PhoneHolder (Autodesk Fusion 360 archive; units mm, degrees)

design "PhoneHolderScrew" references "PhoneClamp"
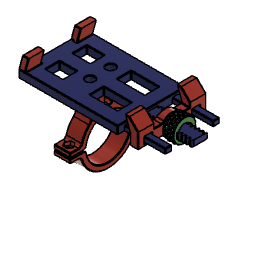
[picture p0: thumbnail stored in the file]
parameter "ScrewTolerance" = 0.1
parameter "NutTolerance" = 0
sketch "Sketch1" plane through (0, 0, 0) normal (0, 0, 1) x axis (1, 0, 0)
  line L1 (-12.5, 50) -> (-85, 50)
  line L2 (-12.5, 0) -> (-12.5, 50)
  line L3 (-85, 0) -> (-12.5, 0)
  line L4 (-85, 50) -> (-85, 0)
  line L5 (-52.5, 20) -> (-52.5, 35)
  line L6 (-80, 48) -> (-83, 48)
  line L7 (-80, 38) -> (-80, 48)
  line L8 (-83, 38) -> (-80, 38)
  line L9 (-83, 48) -> (-83, 38)
  line L10 (-80, 2) -> (-83, 2)
  line L11 (-80, 12) -> (-80, 2)
  line L12 (-83, 12) -> (-80, 12)
  line L13 (-83, 2) -> (-83, 12)
  line L14 (17.5, 45) -> (-12.5, 45)
  line L15 (17.5, 40) -> (17.5, 45)
  line L16 (-12.5, 40) -> (17.5, 40)
  line L17 (-12.5, 45) -> (-12.5, 40)
  line L18 (17.5, 5) -> (-12.5, 5)
  line L19 (17.5, 10) -> (17.5, 5)
  line L20 (-12.5, 10) -> (17.5, 10)
  line L21 (-12.5, 5) -> (-12.5, 10)
  line L22 (-80, 25) -> (-12.5, 25)
  line L23 (-22.5, 40) -> (-42.5, 40)
  line L24 (-22.5, 30) -> (-22.5, 40)
  line L25 (-42.5, 30) -> (-22.5, 30)
  line L26 (-42.5, 40) -> (-42.5, 30)
  line L27 (-22.5, 20) -> (-42.5, 20)
  line L28 (-22.5, 10) -> (-22.5, 20)
  line L29 (-42.5, 10) -> (-22.5, 10)
  line L30 (-42.5, 20) -> (-42.5, 10)
  line L31 (-75, 30) -> (-62.5, 30)
  line L32 (-75, 40) -> (-75, 30)
  line L33 (-62.5, 40) -> (-75, 40)
  line L34 (-62.5, 30) -> (-62.5, 40)
  line L35 (-75, 10) -> (-62.5, 10)
  line L36 (-75, 20) -> (-75, 10)
  line L37 (-62.5, 20) -> (-75, 20)
  line L38 (-62.5, 10) -> (-62.5, 20)
  circle C1 centre (-52.5, 35) radius 1.75
  circle C2 centre (-52.5, 20) radius 1.75
  circle C3 centre (-52.5, 35) radius 3
  circle C4 centre (-52.5, 20) radius 3
  point P6 (-52.5, 35)
  point P8 (-52.5, 35)
  point P7 (-52.5, 20)
  point P9 (-52.5, 20)
  point P20 (-12.5, 45)
  point P24 (-12.5, 5)
  point P28 (-12.5, 25)
  point P2 (-85, 50)
  point P3 (-12.5, 50)
  point P5 (-85, 0)
  point P10 (-52.5, 35)
  point P21 (17.5, 45)
  horizontal L1
  vertical L2
  horizontal L3
  vertical L4
  vertical L5
  coincident P6 P8
  coincident P7 P9
  concentric C1 C3
  concentric C2 C4
  horizontal L6
  vertical L7
  horizontal L8
  vertical L9
  horizontal L10
  vertical L11
  horizontal L12
  vertical L13
  horizontal L14
  vertical L15
  horizontal L16
  vertical L17
  coincident L2 P20
  horizontal L18
  vertical L19
  horizontal L20
  vertical L21
  coincident L2 P24
  midpoint L2 P28
  perpendicular L5 L22
  horizontal L23
  vertical L24
  horizontal L25
  vertical L26
  horizontal L27
  vertical L28
  horizontal L29
  vertical L30
  horizontal L31
  vertical L32
  horizontal L33
  vertical L34
  horizontal L35
  vertical L36
  horizontal L37
  vertical L38
  dimension "d1" distance P2 P3 = 72.5
  dimension "d2" distance P2 P5 = 50
  dimension "d3" distance P6 P7 = 15
  dimension "d4" diameter C1 = 3.5
  dimension "d5" diameter C2 = 3.5
  dimension "d6" diameter C3 = 6
  dimension "d7" diameter C4 = 6
  dimension "d8" distance L4 L5 = 32.5
  dimension "d9" distance L1 P10 = 15
  dimension "d10" distance L6 L8 = 10
  dimension "d11" distance L7 L9 = 3
  dimension "d12" distance L1 L6 = 2
  dimension "d13" distance L4 L9 = 2
  dimension "d14" distance L10 L12 = 10
  dimension "d15" distance L11 L13 = 3
  dimension "d16" distance L4 L13 = 2
  dimension "d17" distance L3 L10 = 2
  dimension "d18" distance P20 P21 = 30 (= "d21")
  dimension "d19" distance L14 L16 = 5
  dimension "d20" distance L1 L14 = 5
  dimension "d21" distance L2 L19 = 30
  dimension "d22" distance L18 L20 = 5
  dimension "d23" distance L3 L18 = 5
  dimension "d186" distance L32 L34 = 12.5
  dimension "d187" distance L36 L38 = 12.5 (= "d186")
  dimension "d188" distance L4 L32 = 10
  dimension "d189" distance L4 L36 = 10 (= "d188")
  dimension "d190" distance L2 L24 = 10
  dimension "d191" distance L2 L28 = 10 (= "d190")
  dimension "d192" distance L24 L26 = 20
  dimension "d193" distance L28 L30 = 20 (= "d192")
  dimension "d194" distance L23 L25 = 10
  dimension "d195" distance L27 L29 = 10 (= "d194")
extrude "Extrude1" new body sketch "Sketch1" profile of L1 L2 L3 L4 C1 C2 C3 C4 L6 L7 L8 L9 L10 L11 L12 L13 L14 L15 L16 L17 L18 L19 L20 L21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 along normal blind 1.2
extrude "Extrude2" add sketch "Sketch1" profile of L1 L2 L3 L4 C3 C4 L6 L7 L8 L9 L10 L11 L12 L13 L17 L21 L23 L24 L25 L26 L27 L28 L29 L30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 along normal blind 6
extrude "Extrude9" add sketch "Sketch1" profile of L2 L14 L15 L16 L17 L18 L19 L20 L21 along normal blind 4
work_plane "WorkPlane1" AlongDistance 0
sketch "Sketch2" plane through (-81.5, 48, 2.5) normal (0, -1, 0) x axis (1, 0, 0)
  line L1 (1.2, 3.5) -> (-1.5, 3.5)
  line L2 (1.2, -2.5) -> (1.2, 3.5)
  line L3 (-1.5, -2.5) -> (1.2, -2.5)
  line L4 (-1.5, 3.5) -> (-1.5, -2.5)
  line L5 (-3.5, 3.5) -> (-1.5, 3.5)
  line L6 (8, 13.5) -> (-3.5, 13.5)
  line L7 (3.8795, 13.5) -> (1.2, 3.5)
  line L8 (11.6528, 3.5) -> (1.2, 3.5)
  line L9 (-0.8205, 13.5) -> (-3.5, 3.5)
  line L10 (6.8528, 3.5) -> (-3.5, 3.5)
  point P9 (3.8795, 13.5)
  point P11 (-0.8205, 13.5)
  point P2 (-1.5, 3.5)
  point P3 (1.2, 3.5)
  point P5 (-1.5, -2.5)
  horizontal L1
  vertical L2
  horizontal L3
  vertical L4
  perpendicular L4 L5
  horizontal L8
  coincident L6 P9
  horizontal L10
  coincident L6 P11
  dimension "d37" distance P2 P3 = 2.7
  dimension "d38" distance P2 P5 = 6
  dimension "d39" angle L7 L8 = 75
  dimension "d40" angle L9 L10 = 75
extrude "Extrude3" new body sketch "Sketch2" profile of L1 L2 L3 L4 L5 L6 L7 L9 along normal blind 9.8
extrude "Extrude4" add sketch "Sketch2" profile of L1 L5 L6 L7 L9 against normal blind 2
extrude "Extrude5" new body sketch "Sketch2" profile of L1 L2 L3 L4 L5 L6 L7 L9 blind 9.8 from offset 36.2
extrude "Extrude6" add sketch "Sketch2" profile of L1 L5 L6 L7 L9 blind 2 from offset 46
sketch "Sketch7" plane through (-12.5, 0, 0) normal (1, 0, 0) x axis (0, 1, 0)
  line L1 (40, 4) -> (40, 0)
  line L2 (45, 4) -> (40, 4)
  line L3 (45, 0) -> (45, 4)
  line L4 (50, 0) -> (45, 0)
  line L5 (50, 6) -> (50, 0)
  line L6 (0, 6) -> (50, 6)
  line L7 (0, 0) -> (0, 6)
  line L8 (5, 0) -> (0, 0)
  line L9 (5, 4) -> (5, 0)
  line L10 (10, 4) -> (5, 4)
  line L11 (10, 0) -> (10, 4)
  line L12 (40, 0) -> (10, 0)
  line L13 (28, 4) -> (22, 4)
  line L14 (28, 0) -> (28, 4)
  line L15 (22, 0) -> (28, 0)
  line L16 (22, 4) -> (22, 0)
  line L17 (28, 0) -> (22, 4)
  line L18 (22, 0) -> (28, 4)
  line L19 (19.3431, 4) -> (22, 4)
  line L20 (30.6569, 4) -> (28, 4)
  circle C1 centre (25, 2) radius 6
  point P18 (25, 2)
  point P19 (19.3431, 4)
  point P20 (30.6569, 4)
  point P14 (22, 4)
  point P15 (28, 4)
  point P17 (22, 0)
  horizontal L13
  vertical L14
  horizontal L15
  vertical L16
  midpoint L17 P18
  coincident C1 P19
  perpendicular L16 L19
  coincident C1 P20
  perpendicular L14 L20
  dimension "d125" distance P14 P15 = 6
  dimension "d126" distance P14 P17 = 4
  dimension "d127" diameter C1 = 12
extrude "Extrude16" add sketch "Sketch7" profile of L12 L13 L14 L15 L16 C1 L19 L20 along normal blind 35
thread "Thread1"
work_plane "WorkPlane2" AlongDistance 0
sketch "Sketch4" plane through (17.5, 7.5, 2) normal (1, 0, 0) x axis (0, 1, 0)
  line L1 (42.5, 4) -> (-7.5, 4)
  line L2 (42.5, -4) -> (42.5, 4)
  line L3 (-7.5, -4) -> (42.5, -4)
  line L4 (-7.5, 4) -> (-7.5, -4)
  line L5 (2.5, 2) -> (-2.5, 2)
  line L6 (2.5, -2) -> (2.5, 2)
  line L7 (-2.5, -2) -> (2.5, -2)
  line L8 (-2.5, 2) -> (-2.5, -2)
  line L9 (37.5, 2) -> (32.5, 2)
  line L10 (37.5, -2) -> (37.5, 2)
  line L11 (32.5, -2) -> (37.5, -2)
  line L12 (32.5, 2) -> (32.5, -2)
  line L13 (32.3, -2.2) -> (37.7, -2.2)
  line L14 (32.3, 2.2) -> (32.3, -2.2)
  line L15 (37.7, 2.2) -> (32.3, 2.2)
  line L16 (37.7, -2.2) -> (37.7, 2.2)
  line L17 (-2.7, -2.2) -> (2.7, -2.2)
  line L18 (-2.7, 2.2) -> (-2.7, -2.2)
  line L19 (2.7, 2.2) -> (-2.7, 2.2)
  line L20 (2.7, -2.2) -> (2.7, 2.2)
  line L21 (23.243, 2.2) -> (11.757, 2.2)
  line L22 (23.243, -2.2) -> (11.757, -2.2)
  circle C1 centre (17.5, 0) radius 6.15
  point P23 (11.757, 2.2)
  point P24 (23.243, 2.2)
  point P25 (11.757, -2.2)
  point P26 (23.243, -2.2)
  point P22 (17.5, 0)
  horizontal L1
  vertical L2
  horizontal L3
  vertical L4
  horizontal L5
  vertical L6
  horizontal L7
  vertical L8
  horizontal L9
  vertical L10
  horizontal L11
  vertical L12
  coincident C1 P23
  coincident C1 P24
  horizontal L21
  coincident C1 P25
  coincident C1 P26
  parallel L3 L22
  dimension "d64" distance L2 L4 = 50
  dimension "d65" distance L1 L3 = 8
  dimension "d66" = -0.2
  dimension "d67" = -0.2
  dimension "d130" diameter C1 = 12.3
  dimension "d131" distance L21 L22 = 4.4
  dimension "d132" distance P22 L21 = 2.2 (= "d131 / 2")
extrude "Extrude10" new body sketch "Sketch4" profile of L1 L2 L3 L4 L13 L16 L15 L14 L17 L18 L19 L20 C1 L21 L22 blind -6 from offset -15
sketch "Sketch5" plane through (2.5, 0, 0) normal (1, 0, 0) x axis (0, 1, 0)
  line L1 (45.2, 4.2) -> (39.8, 4.2)
  line L2 (45.2, -0.2) -> (45.2, 4.2)
  line L3 (39.8, -0.2) -> (45.2, -0.2)
  line L4 (39.8, 4.2) -> (39.8, -0.2)
  line L5 (10.2, 4.2) -> (4.8, 4.2)
  line L6 (10.2, -0.2) -> (10.2, 4.2)
  line L7 (4.8, -0.2) -> (10.2, -0.2)
  line L8 (4.8, 4.2) -> (4.8, -0.2)
  line L9 (50, -2) -> (0, -2)
  line L10 (50, 6) -> (50, -2)
  line L11 (0, 6) -> (50, 6)
  line L12 (0, -2) -> (0, 6)
  line L13 (30.799, 6) -> (18.7516, 6)
  line L14 (30.743, 4.2) -> (19.257, 4.2)
  line L15 (19.257, -0.2) -> (30.743, -0.2)
  circle C1 centre (25, 2) radius 7.5
  arc A1 centre (25, 2) radius 6.15 clockwise from (19.257, -0.2) to (19.257, 4.2)
  arc A2 centre (25, 2) radius 6.15 clockwise from (30.743, 4.2) to (30.743, -0.2)
  point P15 (18.7516, 6)
  point P16 (30.799, 6)
  coincident L11 P15
  coincident L11 P16
  dimension "d74" diameter C1 = 15
extrude "Extrude13" add sketch "Sketch5" profile of L9 L11 C1 L13 against normal blind 5
fillet "Fillet1" radius 2.5 2.5
chamfer "Chamfer1" distance 1 distance 3.49 distance 1 distance 3.49
sketch "Sketch6" plane through (0, 0, 0) normal (0, -1, 0) x axis (1, 0, 0)
  line L1 (2.5, 6) -> (2.5, -2)
  line L2 (-3.5, 6) -> (2.5, 6)
  line L3 (-3.5, -2) -> (-3.5, 6)
  line L4 (2.5, -2) -> (-3.5, -2)
  line L5 (-2, 16) -> (-18, 16)
  line L6 (-7.1397, 16) -> (-3.5, 6)
  line L7 (-0.3582, 6) -> (-3.5, 6)
  line L8 (-4.1397, 16) -> (-7.1397, 16)
  line L9 (2.5, 9.3603) -> (-4.1397, 16)
  line L10 (-3.1628, 16) -> (-4.1397, 16)
  line L11 (2.5, 12) -> (2.5, 6)
  point P4 (-3.5, 6)
  point P8 (-3.5, 6)
  point P9 (-7.1397, 16)
  point P3 (2.5, 6)
  point P14 (2.5, 6)
  point P12 (2.5, 9.3603)
  point P11 (-4.1397, 16)
  horizontal L5
  horizontal L7
  coincident P4 P8
  coincident L5 P9
  parallel L5 L8
  horizontal L10
  coincident P3 P14
  perpendicular L7 L11
  coincident P12 L11
  dimension "d82" distance L2 L5 = 10
  dimension "d83" angle L6 L7 = 110
  dimension "d84" distance P9 P11 = 3
  dimension "d85" angle L9 L10 = 45
extrude "Extrude14" add sketch "Sketch6" profile of L2 L5 L6 L8 L9 L11 against normal blind 12
extrude "Extrude15" add sketch "Sketch6" profile of L2 L5 L6 L8 L9 L11 blind 12 from offset -50
chamfer "Chamfer2" distance 0.5 distance 0.5 distance 0.5 distance 0.5 distance 0.5 distance 0.5 distance 0.5 distance 0.5 distance 0.4 distance 0.5 distance 0.5 distance 0.5
component_from_bodies "Body->Comp1"
component_from_bodies "Body->Comp2"
copy_paste_bodies "CutPasteBodies"
component_from_bodies "Body->Comp3"
external_derived "ExternalDerived1" bodies "BottomClamp", "TopClamp"
derived_instance "DerivedInstance1"
derived_instance "DerivedInstance2"
position "Position1"
joint "Assemble2" alignAngle 0 alignOffsetX 0 alignOffsetY 0 alignOffsetZ 0 DistanceMinimum -9 DistanceMaximum 6
joint "Assemble4" alignAngle 0 alignOffsetX 0 alignOffsetY 0 alignOffsetZ 0 AngleMinimum -180 AngleMaximum 0 AngleRest 0
position "Position3"
sketch "Sketch8" plane through (22.5, 0, 0) normal (1, 0, 0) x axis (0, 1, 0)
  curve K1 (21.3346, 0) -> (21.3307, 0.0425)
  line L1 (21.3537, 4) -> (30.5942, 4)
  line L2 (30.5942, 0) -> (21.3346, 0)
  line L3 (36.9296, 2) -> (23.5, 2)
  line L4 (34, -1) -> (34, 5)
  line L5 (33, 2) -> (34, 4)
  line L6 (34, 0) -> (33, 2)
  line L7 (35, 2) -> (34, 0)
  line L8 (34, 4) -> (35, 2)
  circle C1 centre (25, 2) radius 6.1
  circle C2 centre (25, 2) radius 9
  arc A1 centre (25, 2) radius 4.1588 clockwise from (21.3307, 0.0425) to (21.3537, 4)
  arc A2 centre (25, 2) radius 5.941 clockwise from (30.5942, 4) to (30.5942, 0)
  point P8 (25, 2)
  point P12 (34, 4)
  point P14 (34, 0)
  point P15 (35, 2)
  point P13 (33, 2)
  horizontal L3
  coincident L3 P8
  concentric C1 C2
  perpendicular L3 L4
  coincident L4 P12
  coincident L4 P14
  coincident L3 P15
  parallel L5 L7
  parallel L6 L8
  equal L5 L7
  tangent C2 L4
  equal L5 L6
  dimension "d141" diameter C1 = 12.2
  dimension "d142" diameter C2 = 18
  dimension "d143" distance L1 L3 = 2
  dimension "d145" distance P12 P14 = 4 (= "d146 * 2")
  dimension "d146" distance P13 P15 = 2
extrude "Extrude17" new body sketch "Sketch8" profile of C1 C2 L5 L6 against normal blind 8
chamfer "Chamfer3" distance 1
coil_primitive "CoilPrimitive1" Diameter 12 SectionSize 0.6 TaperAngle 0 Revolutions 0.125 Height -8
sweep "Sweep1" sketch "Sketch8" TwistAngle 0 TaperAngle 0
work_plane "WorkPlane3"
mirror "Mirror1" mirrorStitchTolerance 0.1
work_axis "WorkAxis1"
circular_pattern "C-Pattern1" countU 16 TotalAngle 360
thread "Thread2"
move "Move1" RotateAngle 120
component_from_bodies "Body->Comp5"
position "Position4" TranslateAlongX 6
ground "Ground1"
joint "Assemble5" alignAngle 0 alignOffsetX 0 alignOffsetY 0 alignOffsetZ 0 DistanceMinimum -15 DistanceMaximum 0 DistanceRest 0
position "Position5"
motion_link "MotionLink1" Value1 1.75 Value2 360
offset_faces "OffsetFaces1"
offset_faces "OffsetFaces2" distance -0.05
offset_faces "OffsetFaces1"
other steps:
derived_base_feature "Derived Base Feature1" bodies "BottomClamp"
derived_base_feature "Derived Base Feature1" bodies "TopClamp"
base_feature "Base Feature1" bodies "Slider"
base_feature "Base Feature1" bodies "Hook:1"
base_feature "Base Feature2" bodies "Hook:2"
base_feature "Base Feature1" bodies "Nut"
base_feature "Base Feature1" bodies "Base"
create_component "CreateComponent1"
remove_body "RemoveBody1"
create_component "CreateComponent2"
remove_body "RemoveBody2"
remove_body "RemoveBody3"
create_component "CreateComponent3"
remove_body "RemoveBody4"
create_component "CreateComponent4"
create_component "CreateComponent5"
joint_origin "JointOrigin2"
joint_origin "JointOrigin2"
joint_origin "JointOrigin2"
joint_origin "JointOrigin2"
create_component "CreateComponent7"
remove_body "RemoveBody6"
joint_origin "JointOrigin3"
joint_origin "JointOrigin5"
named bodies: "Base", "Hook:1", "Hook:2", "Slider", "BottomClamp", "TopClamp", "Nut"

design "PhoneClamp"
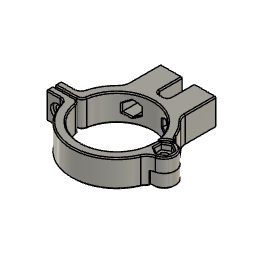
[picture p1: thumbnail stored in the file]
sketch "Sketch1" plane through (0, 0, 0) normal (0, 0, 1) x axis (1, 0, 0)
  line L1 (0, 3.3486) -> (2.9, 1.6743)
  line L2 (-2.9, 1.6743) -> (0, 3.3486)
  line L3 (-2.9, -1.6743) -> (-2.9, 1.6743)
  line L4 (0, -3.3486) -> (-2.9, -1.6743)
  line L5 (2.9, -1.6743) -> (0, -3.3486)
  line L6 (2.9, 1.6743) -> (2.9, -1.6743)
  line L7 (10, 0) -> (0, 0)
  line L8 (-9.853, 0) -> (0, 0)
  line L9 (-9.853, 0) -> (-40, 0)
  line L10 (-41.196, 0.4) -> (-37.195, 0.4)
  line L11 (-37.195, -0.4) -> (-41.196, -0.4)
  line L12 (-49.196, 0.4) -> (-37.195, 0.4)
  line L13 (-49.196, 3.4) -> (-49.196, 0.4)
  line L14 (-37.195, 3.4) -> (-49.196, 3.4)
  line L15 (-37.195, 0.4) -> (-37.195, 3.4)
  line L16 (-49.196, -0.4) -> (-37.195, -0.4)
  line L17 (-49.196, -3.4) -> (-49.196, -0.4)
  line L18 (-37.195, -3.4) -> (-49.196, -3.4)
  line L19 (-37.195, -0.4) -> (-37.195, -3.4)
  line L20 (-21.1, 48.6647) -> (-21.1, 0)
  line L21 (-13.6, 19) -> (-13.6, 45)
  line L22 (-28.6, 19) -> (-28.6, 45)
  line L23 (-33.6, 32.1) -> (-23.6, 32.1)
  line L24 (-33.6, 15.7404) -> (-33.6, 32.1)
  line L25 (-23.6, 15.7404) -> (-33.6, 15.7404)
  line L26 (-23.6, 32.1) -> (-23.6, 15.7404)
  line L27 (-8.6, 32.1) -> (-18.6, 32.1)
  line L28 (-8.6, 15.7404) -> (-8.6, 32.1)
  line L29 (-18.6, 15.7404) -> (-8.6, 15.7404)
  line L30 (-18.6, 32.1) -> (-18.6, 15.7404)
  line L31 (-11, 20.1) -> (-31, 20.1)
  circle C1 centre (0, 0) radius 3
  circle C2 centre (0, 0) radius 5
  circle C3 centre (0, 0) radius 1.75
  circle C4 centre (0, 0) radius 5.25
  circle C5 centre (-21.1, 0) radius 16.1
  circle C6 centre (-21.1, 0) radius 20.1
  point P1 (0, 0)
  point P2 (0, 0)
  point P11 (0, 0)
  point P12 (0, 0)
  point P14 (0, 0)
  point P20 (-37.195, 0.4)
  point P21 (-41.196, 0.4)
  point P22 (-41.196, -0.4)
  point P23 (-37.195, -0.4)
  point P16 (-21.1, 0)
  point P30 (-21.1, 0)
  point P38 (-33.6, 15.7404)
  point P42 (-8.6, 15.7404)
  coincident P1 P2
  concentric C1 C3
  coincident P2 P11
  coincident P1 P12
  perpendicular L6 L7
  coincident P2 P14
  parallel L7 L8
  horizontal L9
  coincident C5 P20
  coincident C6 P21
  parallel L9 L10
  coincident C6 P22
  coincident C5 P23
  parallel L9 L11
  horizontal L12
  vertical L13
  horizontal L14
  vertical L15
  horizontal L16
  vertical L17
  horizontal L18
  vertical L19
  tangent C2 C5
  coincident P16 P30
  vertical L20
  coincident P16 L9
  parallel L20 L21
  vertical L22
  horizontal L23
  vertical L24
  horizontal L25
  vertical L26
  coincident C6 P38
  horizontal L27
  vertical L28
  horizontal L29
  vertical L30
  coincident C6 P42
  perpendicular L21 L31
  tangent C6 L31
  dimension "d1" diameter C1 = 6
  dimension "d2" = 2
  dimension "d3" diameter C3 = 3.5
  dimension "d4" distance P11 L6 = 2.9
  dimension "d23" = 2.25
  dimension "d35" diameter C5 = 32.2
  dimension "d36" = 4
  dimension "d37" distance L10 L11 = 0.8
  dimension "d38" distance L9 L10 = 0.4 (= "d37 / 2")
  dimension "d39" distance P21 L13 = 8
  dimension "d40" distance P22 L17 = 8
  dimension "d41" distance L12 L14 = 3
  dimension "d42" distance L16 L18 = 3
  dimension "d112" distance L20 L22 = 7.5
  dimension "d113" distance L20 L21 = 7.5
  dimension "d114" distance L22 L24 = 5
  dimension "d115" distance L22 L26 = 5
  dimension "d116" distance L21 L30 = 5
  dimension "d117" distance L21 L28 = 5
  dimension "d118" distance L23 L31 = 12
  dimension "d119" distance L27 L31 = 12 (= "d118")
extrude "Extrude8" new body sketch "Sketch1" profile of C1 C2 L1 L2 L3 L4 L5 L6 C4 C5 C6 L10 L11 L12 L13 L14 L15 L16 L17 L18 L19 L23 L24 L25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 along normal blind 3
extrude "Extrude9" add sketch "Sketch1" profile of C1 C2 C3 L1 L2 L3 L4 L5 L6 C4 C5 C6 L10 L11 L12 L13 L14 L15 L16 L17 L18 L19 L23 L24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 blind 3 from offset 3
extrude "Extrude10" add sketch "Sketch1" profile of C1 C2 C3 L1 L2 L3 L4 L5 L6 C4 C5 C6 L11 L16 L17 L18 L19 blind 3.4 from offset 6
extrude "Extrude11" add sketch "Sketch1" profile of C1 C2 L1 L2 L3 L4 L5 L6 C4 C5 C6 L11 L16 L17 L18 L19 blind 2.6 from offset 9.4
extrude "Extrude12" add sketch "Sketch1" profile of C4 C5 C6 L10 L12 L13 L14 L15 L23 L24 L25 L26 L27 L28 L29 L30 blind 6 from offset 6
sketch "Sketch2" plane through (0, -3.4, 0) normal (0, -1, 0) x axis (1, 0, 0)
  line L1 (-40.9104, 0) -> (-49.196, 0)
  line L2 (-40.9104, 12) -> (-40.9104, 0)
  line L3 (-49.196, 12) -> (-40.9104, 12)
  line L4 (-49.196, 0) -> (-49.196, 12)
  line L5 (-47.196, 2.0461) -> (-47.196, 10.8025)
  line L6 (-44.196, 2.7091) -> (-47.046, 4.3546)
  line L7 (-41.346, 4.3546) -> (-44.196, 2.7091)
  line L8 (-41.346, 7.6454) -> (-41.346, 4.3546)
  line L9 (-44.196, 9.2909) -> (-41.346, 7.6454)
  line L10 (-47.046, 7.6454) -> (-44.196, 9.2909)
  line L11 (-47.046, 4.3546) -> (-47.046, 7.6454)
  circle C1 centre (-44.196, 6) radius 3
  circle C2 centre (-44.196, 6) radius 1.75
  point P8 (-44.196, 6)
  point P16 (-44.196, 6)
  vertical L5
  tangent L5 C1
  concentric C1 C2
  coincident P8 P16
  dimension "d57" distance L4 L5 = 2
  dimension "d58" diameter C1 = 6
  dimension "d59" distance L3 P8 = 6
  dimension "d60" diameter C2 = 3.5
  dimension "d61" distance P16 L11 = 2.85
extrude "Extrude13" cut sketch "Sketch2" profile of C2 against normal blind 10
extrude "Extrude14" cut sketch "Sketch2" profile of C1 C2 L6 L7 L8 L9 L10 L11 against normal blind 1.2
extrude "Extrude15" cut sketch "Sketch2" profile of C1 C2 L6 L7 L8 L9 L10 L11 blind -3.4 from offset -4.4
work_plane "WorkPlane1" AlongDistance -12
sketch "Sketch3" plane through (-13.5, 20.1, 6) normal (0, 1, 0) x axis (1, 0, 0)
  line L1 (-4.5, 5.5) -> (4.5, -5.5)
  line L2 (4.5, 5.5) -> (-4.5, -5.5)
  line L3 (-19.5, 5.5) -> (-10.5, -5.5)
  line L4 (-19.5, -5.5) -> (-10.5, 5.5)
  line L5 (0, -3.2909) -> (-2.85, -1.6454)
  line L6 (2.85, -1.6454) -> (0, -3.2909)
  line L7 (2.85, 1.6454) -> (2.85, -1.6454)
  line L8 (0, 3.2909) -> (2.85, 1.6454)
  line L9 (-2.85, 1.6454) -> (0, 3.2909)
  line L10 (-2.85, -1.6454) -> (-2.85, 1.6454)
  line L11 (-15, -3.2909) -> (-17.85, -1.6454)
  line L12 (-12.15, -1.6454) -> (-15, -3.2909)
  line L13 (-12.15, 1.6454) -> (-12.15, -1.6454)
  line L14 (-15, 3.2909) -> (-12.15, 1.6454)
  line L15 (-17.85, 1.6454) -> (-15, 3.2909)
  line L16 (-17.85, -1.6454) -> (-17.85, 1.6454)
  circle C1 centre (0, 0) radius 1.75
  circle C2 centre (-15, 0) radius 1.75
  point P10 (-15, 0)
  point P1 (0, 0)
  point P17 (0, 0)
  point P24 (-15, 0)
  point P25 (0, 0)
  point P26 (-15, 0)
  midpoint L4 P10
  coincident P1 P17
  coincident P10 P24
  coincident P17 P25
  coincident P10 P26
  dimension "d126" distance P17 L10 = 2.85
  dimension "d127" distance P24 L16 = 2.85
  dimension "d128" diameter C1 = 3.5
  dimension "d129" diameter C2 = 3.5
extrude "Extrude16" cut sketch "Sketch3" profile of L5 L6 L7 L8 L9 L10 L11 L12 L13 L14 L15 L16 C1 C2 against normal blind 8
extrude "Extrude17" cut sketch "Sketch3" profile of C1 C2 along normal blind 12
fillet "Fillet2" radius 5 2.5 5 1.5 2.5
chamfer "Chamfer3" distance 0.5 distance 1 distance 0.5 distance 0.5 distance 0.4
component_from_bodies "Body->Comp2"
component_from_bodies "Body->Comp3"
joint "Assemble1" alignAngle 0 alignOffsetX 0 alignOffsetY 0 alignOffsetZ 0 AngleMinimum -180 AngleMaximum 1 AngleRest 0
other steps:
base_feature "Base Feature1"
base_feature "Base Feature1"
create_component "CreateComponent2"
remove_body "RemoveBody3"
create_component "CreateComponent3"
remove_body "RemoveBody5"
joint_origin "JointOrigin4"
joint_origin "JointOrigin4"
